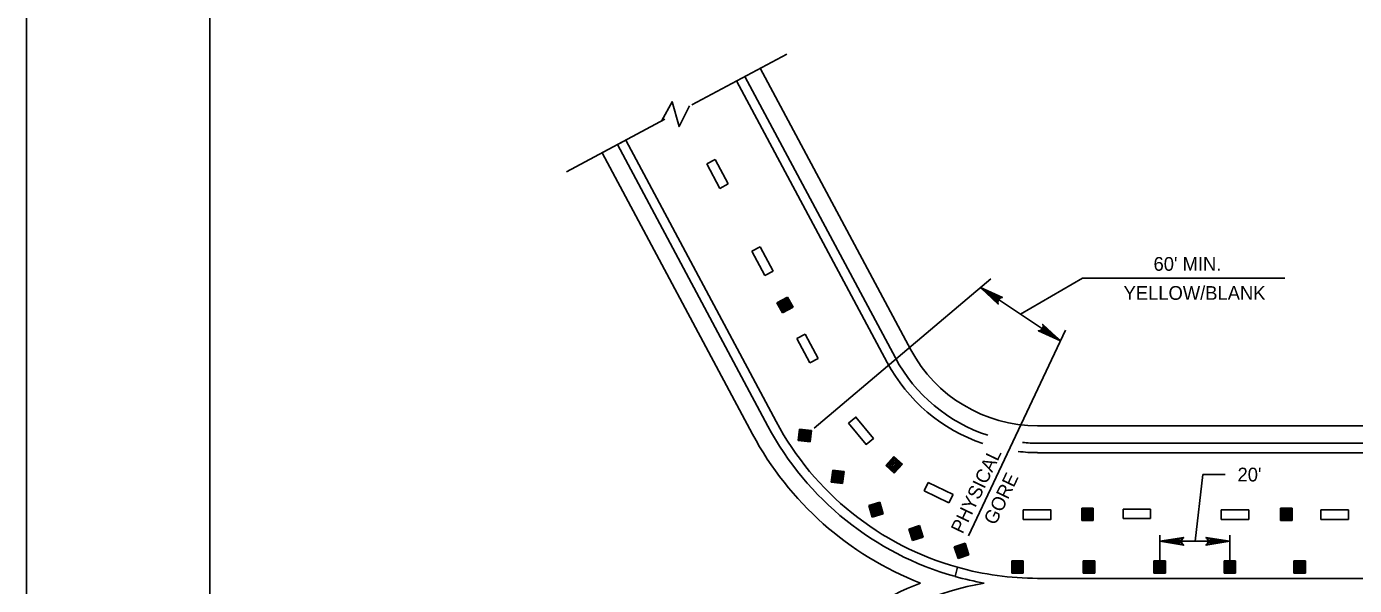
# Model space of a CAD drawing. Extents: x 639362 to 641108, y 298458 to 299646.
# Drawn here: x 639362.3 to 639652.3, y 299227.7 to 299349.9 of the extents above; entities that cross this region are included whole.
import ezdxf

# ---------------------------------------------------------------- set-up
doc = ezdxf.new("R2010")
doc.units = 0
for name, color, linetype in [('1', 7, 'Continuous'), ('2', 7, 'Continuous'), ('PLT-BNDY', 7, 'Continuous')]:
    doc.layers.add(name, color=color, linetype=linetype)

msp = doc.modelspace()

# ---------------------------------------------------------------- linework, layer by layer
at = {"layer": '1'}
msp.add_line((639402.31, 299630.63), (639402.31, 299066.63), dxfattribs=at)
at = {"layer": '2'}
for p, q in [((639507.56, 299332.75), (639528.33, 299343.84)), ((639555.38, 299279.23), (639522.52, 299340.74)), ((639550.22, 299276.47), (639517.36, 299337.98)), ((639552.04, 299277.45), (639519.18, 299338.95)), ((639480.23, 299318.14), (639501.69, 299329.61)), ((639493.13, 299325.03), (639491.31, 299324.06)), ((639491.31, 299324.06), (639524.18, 299262.56)), ((639526, 299263.53), (639493.13, 299325.03)), ((639520.84, 299260.77), (639487.97, 299322.28)), ((639510.86, 299319.82), (639512.69, 299320.78)), ((639513.67, 299314.5), (639510.86, 299319.82)), ((639512.69, 299320.78), (639515.49, 299315.46)), ((639515.49, 299315.46), (639513.67, 299314.5)), ((639520.7, 299300.75), (639522.53, 299301.71)), ((639523.5, 299295.43), (639520.7, 299300.75)), ((639522.53, 299301.71), (639525.33, 299296.39)), ((639525.33, 299296.39), (639523.5, 299295.43)), ((639534.31, 299262.09), (639572.85, 299294.76)), ((639579.34, 299287), (639592.87, 299294.89)), ((639592.87, 299294.89), (639637.03, 299294.89)), ((639526.16, 299289.48), (639528.5, 299290.73)), ((639526.36, 299289.38), (639528.47, 299290.51)), ((639528.47, 299290.51), (639529.48, 299288.63)), ((639528.5, 299290.73), (639529.68, 299288.53)), ((639570.58, 299292.84), (639588.1, 299281.16)), ((639527.34, 299287.28), (639526.16, 299289.48)), ((639527.37, 299287.5), (639526.36, 299289.38)), ((639526.6, 299289.3), (639528.4, 299290.27)), ((639527.44, 299287.74), (639526.6, 299289.3)), ((639526.84, 299289.23), (639528.33, 299290.03)), ((639527.51, 299287.98), (639526.84, 299289.23)), ((639527.08, 299289.16), (639528.25, 299289.79)), ((639527.58, 299288.22), (639527.08, 299289.16)), ((639527.32, 299289.09), (639528.18, 299289.55)), ((639527.66, 299288.46), (639527.32, 299289.09)), ((639529.68, 299288.53), (639527.34, 299287.28)), ((639529.48, 299288.63), (639527.37, 299287.5)), ((639529.24, 299288.7), (639527.44, 299287.74)), ((639529, 299288.78), (639527.51, 299287.98)), ((639527.56, 299289.01), (639528.11, 299289.31)), ((639527.73, 299288.7), (639527.56, 299289.01)), ((639528.76, 299288.85), (639527.58, 299288.22)), ((639528.52, 299288.92), (639527.66, 299288.46)), ((639528.28, 299288.99), (639527.73, 299288.7)), ((639528.04, 299289.07), (639527.8, 299288.94)), ((639528.11, 299289.31), (639528.28, 299288.99)), ((639528.18, 299289.55), (639528.52, 299288.92)), ((639528.25, 299289.79), (639528.76, 299288.85)), ((639528.33, 299290.03), (639529, 299288.78)), ((639528.4, 299290.27), (639529.24, 299288.7)), ((639530.53, 299281.68), (639532.36, 299282.65)), ((639532.36, 299282.65), (639535.16, 299277.33)), ((639568.01, 299238.58), (639589.2, 299283.5)), ((639533.34, 299276.36), (639530.53, 299281.68)), ((639535.16, 299277.33), (639533.34, 299276.36)), ((639530.8, 299259.39), (639531.06, 299261.87)), ((639530.95, 299259.56), (639531.17, 299261.68)), ((639531.06, 299261.87), (639533.7, 299261.59)), ((639531.14, 299259.72), (639531.33, 299261.48)), ((639531.17, 299261.68), (639533.55, 299261.43)), ((639531.33, 299261.48), (639533.36, 299261.27)), ((639533.7, 299261.59), (639533.44, 299259.11)), ((639583.1, 299262.59), (639789.68, 299262.59)), ((639533.44, 299259.11), (639530.8, 299259.39)), ((639533.33, 299259.31), (639530.95, 299259.56)), ((639533.17, 299259.51), (639531.14, 299259.72)), ((639531.34, 299259.88), (639531.49, 299261.29)), ((639533.02, 299259.7), (639531.34, 299259.88)), ((639531.49, 299261.29), (639533.17, 299261.11)), ((639531.53, 299260.03), (639531.65, 299261.09)), ((639532.86, 299259.89), (639531.53, 299260.03)), ((639531.65, 299261.09), (639532.97, 299260.95)), ((639531.73, 299260.19), (639531.8, 299260.9)), ((639532.7, 299260.09), (639531.73, 299260.19)), ((639531.8, 299260.9), (639532.78, 299260.8)), ((639531.93, 299260.35), (639531.96, 299260.7)), ((639532.54, 299260.29), (639531.93, 299260.35)), ((639531.96, 299260.7), (639532.58, 299260.64)), ((639532.12, 299260.51), (639532.38, 299260.48)), ((639532.58, 299260.64), (639532.54, 299260.29)), ((639532.78, 299260.8), (639532.7, 299260.09)), ((639532.97, 299260.95), (639532.86, 299259.89)), ((639533.17, 299261.11), (639533.02, 299259.7)), ((639533.36, 299261.27), (639533.17, 299259.51)), ((639533.55, 299261.43), (639533.33, 299259.31)), ((639583.09, 299258.81), (639789.68, 299258.81)), ((639549.93, 299253.95), (639551.72, 299255.91)), ((639550.15, 299253.92), (639551.77, 299255.69)), ((639551.72, 299255.91), (639553.56, 299254.22)), ((639551.77, 299255.69), (639553.34, 299254.25)), ((639583.09, 299256.74), (639789.68, 299256.74)), ((639538.03, 299250.32), (639538.4, 299252.95)), ((639538.23, 299250.43), (639538.57, 299252.8)), ((639538.4, 299252.95), (639540.87, 299252.6)), ((639538.57, 299252.8), (639540.67, 299252.5)), ((639551.77, 299252.27), (639549.93, 299253.95)), ((639551.72, 299252.48), (639550.15, 299253.92)), ((639550.41, 299253.93), (639551.78, 299255.44)), ((639551.71, 299252.74), (639550.41, 299253.93)), ((639550.65, 299253.94), (639551.79, 299255.19)), ((639551.7, 299252.99), (639550.65, 299253.94)), ((639550.9, 299253.96), (639551.8, 299254.94)), ((639551.69, 299253.24), (639550.9, 299253.96)), ((639551.15, 299253.97), (639551.81, 299254.69)), ((639551.68, 299253.49), (639551.15, 299253.97)), ((639551.41, 299253.98), (639551.83, 299254.43)), ((639551.67, 299253.74), (639551.41, 299253.98)), ((639551.84, 299254.19), (639551.66, 299253.99)), ((639552.09, 299254.19), (639551.67, 299253.74)), ((639552.34, 299254.21), (639551.68, 299253.49)), ((639552.59, 299254.22), (639551.69, 299253.24)), ((639552.84, 299254.23), (639551.7, 299252.99)), ((639553.09, 299254.24), (639551.71, 299252.74)), ((639553.34, 299254.25), (639551.72, 299252.48)), ((639553.56, 299254.22), (639551.77, 299252.27)), ((639551.78, 299255.44), (639553.09, 299254.24)), ((639551.79, 299255.19), (639552.84, 299254.23)), ((639551.8, 299254.94), (639552.59, 299254.22)), ((639551.81, 299254.69), (639552.34, 299254.21)), ((639551.83, 299254.43), (639552.09, 299254.19)), ((639540.5, 299249.98), (639538.03, 299250.32)), ((639540.34, 299250.13), (639538.23, 299250.43)), ((639538.43, 299250.58), (639538.71, 299252.6)), ((639540.19, 299250.33), (639538.43, 299250.58)), ((639538.63, 299250.73), (639538.87, 299252.4)), ((639540.04, 299250.53), (639538.63, 299250.73)), ((639538.71, 299252.6), (639540.47, 299252.35)), ((639538.83, 299250.88), (639539.02, 299252.2)), ((639539.89, 299250.73), (639538.83, 299250.88)), ((639538.87, 299252.4), (639540.27, 299252.2)), ((639539.02, 299252.2), (639540.07, 299252.05)), ((639539.03, 299251.03), (639539.17, 299252)), ((639539.74, 299250.94), (639539.03, 299251.03)), ((639539.17, 299252), (639539.87, 299251.9)), ((639539.23, 299251.18), (639539.32, 299251.8)), ((639539.58, 299251.14), (639539.23, 299251.18)), ((639539.32, 299251.8), (639539.67, 299251.75)), ((639539.43, 299251.34), (639539.47, 299251.6)), ((639539.67, 299251.75), (639539.58, 299251.14)), ((639539.87, 299251.9), (639539.74, 299250.94)), ((639540.07, 299252.05), (639539.89, 299250.73)), ((639540.27, 299252.2), (639540.04, 299250.53)), ((639540.47, 299252.35), (639540.19, 299250.33)), ((639540.67, 299252.5), (639540.34, 299250.13)), ((639540.87, 299252.6), (639540.5, 299249.98)), ((639558.31, 299248.37), (639559.21, 299250.23)), ((639559.21, 299250.23), (639564.62, 299247.61)), ((639619.18, 299251.99), (639617.48, 299237.38)), ((639619.18, 299251.99), (639624.04, 299251.99)), ((639563.72, 299245.75), (639558.31, 299248.37)), ((639564.62, 299247.61), (639563.72, 299245.75)), ((639546.25, 299245.23), (639548.65, 299245.91)), ((639546.97, 299242.68), (639546.25, 299245.23)), ((639546.46, 299245.16), (639548.51, 299245.74)), ((639547.11, 299242.85), (639546.46, 299245.16)), ((639546.68, 299245.03), (639548.39, 299245.51)), ((639547.23, 299243.07), (639546.68, 299245.03)), ((639546.9, 299244.91), (639548.26, 299245.3)), ((639547.36, 299243.29), (639546.9, 299244.91)), ((639547.12, 299244.79), (639548.14, 299245.08)), ((639547.48, 299243.51), (639547.12, 299244.79)), ((639547.34, 299244.67), (639548.02, 299244.86)), ((639547.6, 299243.73), (639547.34, 299244.67)), ((639547.55, 299244.54), (639547.9, 299244.64)), ((639547.72, 299243.95), (639547.55, 299244.54)), ((639547.85, 299244.17), (639547.78, 299244.42)), ((639547.9, 299244.64), (639548.06, 299244.04)), ((639548.02, 299244.86), (639548.29, 299243.92)), ((639548.14, 299245.08), (639548.5, 299243.8)), ((639548.26, 299245.3), (639548.72, 299243.68)), ((639548.39, 299245.51), (639548.94, 299243.55)), ((639548.51, 299245.74), (639549.16, 299243.43)), ((639548.65, 299245.91), (639549.37, 299243.35)), ((639592.74, 299244.59), (639595.23, 299244.59)), ((639592.74, 299241.93), (639592.74, 299244.59)), ((639592.92, 299244.45), (639595.05, 299244.45)), ((639592.92, 299242.06), (639592.92, 299244.45)), ((639593.1, 299244.28), (639594.87, 299244.28)), ((639593.1, 299242.24), (639593.1, 299244.28)), ((639593.28, 299244.1), (639594.7, 299244.1)), ((639593.28, 299242.41), (639593.28, 299244.1)), ((639594.7, 299244.1), (639594.7, 299242.41)), ((639594.87, 299244.28), (639594.87, 299242.24)), ((639595.05, 299244.45), (639595.05, 299242.06)), ((639595.23, 299244.59), (639595.23, 299241.93)), ((639601.74, 299242.34), (639601.74, 299244.4)), ((639601.74, 299244.4), (639607.75, 299244.4)), ((639607.75, 299244.4), (639607.75, 299242.34)), ((639623.19, 299242.15), (639623.19, 299244.22)), ((639623.19, 299244.22), (639629.21, 299244.22)), ((639629.21, 299244.22), (639629.21, 299242.15)), ((639638.65, 299244.59), (639636.15, 299244.59)), ((639636.15, 299244.59), (639636.15, 299241.93)), ((639638.46, 299244.45), (639636.33, 299244.45)), ((639636.33, 299244.45), (639636.33, 299242.06)), ((639638.28, 299244.28), (639636.51, 299244.28)), ((639636.51, 299244.28), (639636.51, 299242.24)), ((639638.1, 299244.1), (639636.69, 299244.1)), ((639636.69, 299244.1), (639636.69, 299242.41)), ((639638.1, 299242.41), (639638.1, 299244.1)), ((639638.28, 299242.24), (639638.28, 299244.28)), ((639638.46, 299242.06), (639638.46, 299244.45)), ((639638.65, 299241.93), (639638.65, 299244.59)), ((639644.92, 299242.15), (639644.92, 299244.22)), ((639644.92, 299244.22), (639650.93, 299244.22)), ((639650.93, 299244.22), (639650.93, 299242.15)), ((639549.37, 299243.35), (639546.97, 299242.68)), ((639549.16, 299243.43), (639547.11, 299242.85)), ((639548.94, 299243.55), (639547.23, 299243.07)), ((639548.72, 299243.68), (639547.36, 299243.29)), ((639548.5, 299243.8), (639547.48, 299243.51)), ((639548.29, 299243.92), (639547.6, 299243.73)), ((639548.06, 299244.04), (639547.72, 299243.95)), ((639595.23, 299241.93), (639592.74, 299241.93)), ((639595.05, 299242.06), (639592.92, 299242.06)), ((639594.87, 299242.24), (639593.1, 299242.24)), ((639594.7, 299242.41), (639593.28, 299242.41)), ((639593.45, 299243.92), (639594.52, 299243.92)), ((639593.45, 299242.59), (639593.45, 299243.92)), ((639594.52, 299242.59), (639593.45, 299242.59)), ((639593.63, 299242.77), (639593.63, 299243.74)), ((639593.63, 299243.74), (639594.34, 299243.74)), ((639594.34, 299242.77), (639593.63, 299242.77)), ((639593.81, 299243.57), (639594.17, 299243.57)), ((639593.81, 299242.95), (639593.81, 299243.57)), ((639594.17, 299242.95), (639593.81, 299242.95)), ((639593.99, 299243.39), (639593.99, 299243.12)), ((639594.17, 299243.57), (639594.17, 299242.95)), ((639594.34, 299243.74), (639594.34, 299242.77)), ((639594.52, 299243.92), (639594.52, 299242.59)), ((639607.75, 299242.34), (639601.74, 299242.34)), ((639629.21, 299242.15), (639623.19, 299242.15)), ((639636.15, 299241.93), (639638.65, 299241.93)), ((639636.33, 299242.06), (639638.46, 299242.06)), ((639636.51, 299242.24), (639638.28, 299242.24)), ((639636.69, 299242.41), (639638.1, 299242.41)), ((639637.93, 299243.92), (639636.86, 299243.92)), ((639636.86, 299243.92), (639636.86, 299242.59)), ((639636.86, 299242.59), (639637.93, 299242.59)), ((639637.04, 299243.74), (639637.04, 299242.77)), ((639637.75, 299243.74), (639637.04, 299243.74)), ((639637.04, 299242.77), (639637.75, 299242.77)), ((639637.57, 299243.57), (639637.22, 299243.57)), ((639637.22, 299243.57), (639637.22, 299242.95)), ((639637.22, 299242.95), (639637.57, 299242.95)), ((639637.4, 299243.39), (639637.4, 299243.12)), ((639637.57, 299242.95), (639637.57, 299243.57)), ((639637.75, 299242.77), (639637.75, 299243.74)), ((639637.93, 299242.59), (639637.93, 299243.92)), ((639650.93, 299242.15), (639644.92, 299242.15)), ((639554.93, 299240.05), (639557.31, 299240.82)), ((639555.75, 299237.52), (639554.93, 299240.05)), ((639555.14, 299239.98), (639557.17, 299240.64)), ((639555.88, 299237.71), (639555.14, 299239.98)), ((639555.37, 299239.87), (639557.05, 299240.41)), ((639555.99, 299237.93), (639555.37, 299239.87)), ((639555.59, 299239.76), (639556.94, 299240.19)), ((639556.11, 299238.15), (639555.59, 299239.76)), ((639558.12, 299238.29), (639555.75, 299237.52)), ((639555.81, 299239.64), (639556.83, 299239.97)), ((639556.22, 299238.37), (639555.81, 299239.64)), ((639557.9, 299238.36), (639555.88, 299237.71)), ((639557.68, 299238.47), (639555.99, 299237.93)), ((639556.03, 299239.53), (639556.71, 299239.75)), ((639556.33, 299238.6), (639556.03, 299239.53)), ((639557.46, 299238.59), (639556.11, 299238.15)), ((639557.24, 299238.7), (639556.22, 299238.37)), ((639556.26, 299239.41), (639556.6, 299239.52)), ((639556.45, 299238.82), (639556.26, 299239.41)), ((639557.01, 299238.82), (639556.33, 299238.6)), ((639556.79, 299238.93), (639556.45, 299238.82)), ((639556.57, 299239.04), (639556.48, 299239.3)), ((639556.6, 299239.52), (639556.79, 299238.93)), ((639556.71, 299239.75), (639557.01, 299238.82)), ((639556.83, 299239.97), (639557.24, 299238.7)), ((639556.94, 299240.19), (639557.46, 299238.59)), ((639557.05, 299240.41), (639557.68, 299238.47)), ((639557.17, 299240.64), (639557.9, 299238.36)), ((639557.31, 299240.82), (639558.12, 299238.29)), ((639609.74, 299238.7), (639609.74, 299232.09)), ((639625.08, 299238.7), (639625.08, 299232.09)), ((639564.89, 299236.17), (639567.26, 299236.94)), ((639565.7, 299233.64), (639564.89, 299236.17)), ((639565.1, 299236.1), (639567.13, 299236.76)), ((639565.84, 299233.83), (639565.1, 299236.1)), ((639565.32, 299235.99), (639567.01, 299236.53)), ((639565.95, 299234.05), (639565.32, 299235.99)), ((639565.55, 299235.88), (639566.9, 299236.31)), ((639566.07, 299234.27), (639565.55, 299235.88)), ((639565.77, 299235.76), (639566.78, 299236.09)), ((639566.18, 299234.49), (639565.77, 299235.76)), ((639565.99, 299235.65), (639566.67, 299235.87)), ((639566.29, 299234.72), (639565.99, 299235.65)), ((639566.22, 299235.53), (639566.55, 299235.64)), ((639566.41, 299234.94), (639566.22, 299235.53)), ((639566.52, 299235.16), (639566.44, 299235.42)), ((639566.55, 299235.64), (639566.74, 299235.05)), ((639566.67, 299235.87), (639566.97, 299234.94)), ((639566.78, 299236.09), (639567.19, 299234.82)), ((639566.9, 299236.31), (639567.41, 299234.71)), ((639567.01, 299236.53), (639567.64, 299234.59)), ((639567.13, 299236.76), (639567.86, 299234.48)), ((639567.26, 299236.94), (639568.08, 299234.41)), ((639609.74, 299237.38), (639625.08, 299237.38)), ((639568.08, 299234.41), (639565.7, 299233.64)), ((639567.86, 299234.48), (639565.84, 299233.83)), ((639567.64, 299234.59), (639565.95, 299234.05)), ((639567.41, 299234.71), (639566.07, 299234.27)), ((639567.19, 299234.82), (639566.18, 299234.49)), ((639566.97, 299234.94), (639566.29, 299234.72)), ((639566.74, 299235.05), (639566.41, 299234.94)), ((639577.44, 299230.43), (639577.44, 299233.09)), ((639577.44, 299233.09), (639579.94, 299233.09)), ((639577.62, 299230.57), (639577.62, 299232.96)), ((639577.62, 299232.96), (639579.75, 299232.96)), ((639577.8, 299230.74), (639577.8, 299232.78)), ((639577.8, 299232.78), (639579.57, 299232.78)), ((639577.98, 299230.92), (639577.98, 299232.61)), ((639577.98, 299232.61), (639579.4, 299232.61)), ((639579.4, 299232.61), (639579.4, 299230.92)), ((639579.57, 299232.78), (639579.57, 299230.74)), ((639579.75, 299232.96), (639579.75, 299230.57)), ((639579.94, 299233.09), (639579.94, 299230.43)), ((639593.04, 299230.43), (639593.04, 299233.09)), ((639593.04, 299233.09), (639595.54, 299233.09)), ((639593.23, 299230.57), (639593.23, 299232.96)), ((639593.23, 299232.96), (639595.35, 299232.96)), ((639593.4, 299230.74), (639593.4, 299232.78)), ((639593.4, 299232.78), (639595.18, 299232.78)), ((639593.58, 299230.92), (639593.58, 299232.61)), ((639593.58, 299232.61), (639595, 299232.61)), ((639595, 299232.61), (639595, 299230.92)), ((639595.18, 299232.78), (639595.18, 299230.74)), ((639595.35, 299232.96), (639595.35, 299230.57)), ((639595.54, 299233.09), (639595.54, 299230.43)), ((639610.97, 299233.09), (639608.47, 299233.09)), ((639608.47, 299233.09), (639608.47, 299230.43)), ((639610.79, 299232.96), (639608.66, 299232.96)), ((639608.66, 299232.96), (639608.66, 299230.57)), ((639610.61, 299232.78), (639608.84, 299232.78)), ((639608.84, 299232.78), (639608.84, 299230.74)), ((639610.43, 299232.61), (639609.01, 299232.61)), ((639609.01, 299232.61), (639609.01, 299230.92)), ((639610.43, 299230.92), (639610.43, 299232.61)), ((639610.61, 299230.74), (639610.61, 299232.78)), ((639610.79, 299230.57), (639610.79, 299232.96)), ((639610.97, 299230.43), (639610.97, 299233.09)), ((639626.31, 299233.09), (639623.81, 299233.09)), ((639623.81, 299233.09), (639623.81, 299230.43)), ((639626.12, 299232.96), (639623.99, 299232.96)), ((639623.99, 299232.96), (639623.99, 299230.57)), ((639625.95, 299232.78), (639624.17, 299232.78)), ((639624.17, 299232.78), (639624.17, 299230.74)), ((639625.77, 299232.61), (639624.35, 299232.61)), ((639624.35, 299232.61), (639624.35, 299230.92)), ((639625.77, 299230.92), (639625.77, 299232.61)), ((639625.95, 299230.74), (639625.95, 299232.78)), ((639626.12, 299230.57), (639626.12, 299232.96)), ((639626.31, 299230.43), (639626.31, 299233.09)), ((639639.06, 299230.43), (639639.06, 299233.09)), ((639639.06, 299233.09), (639641.55, 299233.09)), ((639639.24, 299230.57), (639639.24, 299232.96)), ((639639.24, 299232.96), (639641.37, 299232.96)), ((639639.42, 299230.74), (639639.42, 299232.78)), ((639639.42, 299232.78), (639641.19, 299232.78)), ((639639.6, 299230.92), (639639.6, 299232.61)), ((639639.6, 299232.61), (639641.01, 299232.61)), ((639641.01, 299232.61), (639641.01, 299230.92)), ((639641.19, 299232.78), (639641.19, 299230.74)), ((639641.37, 299232.96), (639641.37, 299230.57)), ((639641.55, 299233.09), (639641.55, 299230.43)), ((639565.05, 299229.71), (639565.61, 299231.69)), ((639579.94, 299230.43), (639577.44, 299230.43)), ((639579.75, 299230.57), (639577.62, 299230.57)), ((639579.57, 299230.74), (639577.8, 299230.74)), ((639579.4, 299230.92), (639577.98, 299230.92)), ((639578.16, 299231.1), (639578.16, 299232.43)), ((639578.16, 299232.43), (639579.22, 299232.43)), ((639579.22, 299231.1), (639578.16, 299231.1)), ((639578.33, 299231.28), (639578.33, 299232.25)), ((639578.33, 299232.25), (639579.04, 299232.25)), ((639579.04, 299231.28), (639578.33, 299231.28)), ((639578.51, 299231.45), (639578.51, 299232.07)), ((639578.51, 299232.07), (639578.86, 299232.07)), ((639578.86, 299231.45), (639578.51, 299231.45)), ((639578.69, 299231.63), (639578.69, 299231.9)), ((639578.86, 299232.07), (639578.86, 299231.45)), ((639579.04, 299232.25), (639579.04, 299231.28)), ((639579.22, 299232.43), (639579.22, 299231.1)), ((639595.54, 299230.43), (639593.04, 299230.43)), ((639595.35, 299230.57), (639593.23, 299230.57)), ((639595.18, 299230.74), (639593.4, 299230.74)), ((639595, 299230.92), (639593.58, 299230.92)), ((639593.76, 299231.1), (639593.76, 299232.43)), ((639593.76, 299232.43), (639594.82, 299232.43)), ((639594.82, 299231.1), (639593.76, 299231.1)), ((639593.93, 299231.28), (639593.93, 299232.25)), ((639593.93, 299232.25), (639594.65, 299232.25)), ((639594.65, 299231.28), (639593.93, 299231.28)), ((639594.11, 299231.45), (639594.11, 299232.07)), ((639594.11, 299232.07), (639594.47, 299232.07)), ((639594.47, 299231.45), (639594.11, 299231.45)), ((639594.29, 299231.63), (639594.29, 299231.9)), ((639594.47, 299232.07), (639594.47, 299231.45)), ((639594.65, 299232.25), (639594.65, 299231.28)), ((639594.82, 299232.43), (639594.82, 299231.1)), ((639608.47, 299230.43), (639610.97, 299230.43)), ((639608.66, 299230.57), (639610.79, 299230.57)), ((639608.84, 299230.74), (639610.61, 299230.74)), ((639609.01, 299230.92), (639610.43, 299230.92)), ((639610.25, 299232.43), (639609.19, 299232.43)), ((639609.19, 299232.43), (639609.19, 299231.1)), ((639609.19, 299231.1), (639610.25, 299231.1)), ((639610.08, 299232.25), (639609.37, 299232.25)), ((639609.37, 299232.25), (639609.37, 299231.28)), ((639609.37, 299231.28), (639610.08, 299231.28)), ((639609.9, 299232.07), (639609.55, 299232.07)), ((639609.55, 299232.07), (639609.55, 299231.45)), ((639609.55, 299231.45), (639609.9, 299231.45)), ((639609.72, 299231.63), (639609.72, 299231.9)), ((639609.9, 299231.45), (639609.9, 299232.07)), ((639610.08, 299231.28), (639610.08, 299232.25)), ((639610.25, 299231.1), (639610.25, 299232.43)), ((639623.81, 299230.43), (639626.31, 299230.43)), ((639623.99, 299230.57), (639626.12, 299230.57)), ((639624.17, 299230.74), (639625.95, 299230.74)), ((639624.35, 299230.92), (639625.77, 299230.92)), ((639625.59, 299232.43), (639624.53, 299232.43)), ((639624.53, 299232.43), (639624.53, 299231.1)), ((639624.53, 299231.1), (639625.59, 299231.1)), ((639625.42, 299232.25), (639624.7, 299232.25)), ((639624.7, 299232.25), (639624.7, 299231.28)), ((639624.7, 299231.28), (639625.42, 299231.28)), ((639625.24, 299232.07), (639624.88, 299232.07)), ((639624.88, 299232.07), (639624.88, 299231.45)), ((639624.88, 299231.45), (639625.24, 299231.45)), ((639625.06, 299231.63), (639625.06, 299231.9)), ((639625.24, 299231.45), (639625.24, 299232.07)), ((639625.42, 299231.28), (639625.42, 299232.25)), ((639625.59, 299231.1), (639625.59, 299232.43)), ((639641.55, 299230.43), (639639.06, 299230.43)), ((639641.37, 299230.57), (639639.24, 299230.57)), ((639641.19, 299230.74), (639639.42, 299230.74)), ((639641.01, 299230.92), (639639.6, 299230.92)), ((639639.77, 299231.1), (639639.77, 299232.43)), ((639639.77, 299232.43), (639640.84, 299232.43)), ((639640.84, 299231.1), (639639.77, 299231.1)), ((639639.95, 299231.28), (639639.95, 299232.25)), ((639639.95, 299232.25), (639640.66, 299232.25)), ((639640.66, 299231.28), (639639.95, 299231.28)), ((639640.13, 299231.45), (639640.13, 299232.07)), ((639640.13, 299232.07), (639640.48, 299232.07)), ((639640.48, 299231.45), (639640.13, 299231.45)), ((639640.3, 299231.63), (639640.3, 299231.9)), ((639640.48, 299232.07), (639640.48, 299231.45)), ((639640.66, 299232.25), (639640.66, 299231.28)), ((639640.84, 299232.43), (639640.84, 299231.1)), ((639583.05, 299229.28), (639672.74, 299229.28))]:
    msp.add_line(p, q, dxfattribs=at)
for points in [[(639501.02, 299329.35), (639503.25, 299333.42), (639504.81, 299328), (639507.1, 299332.53)], [(639574.39, 299289.55), (639574.43, 299289.95), (639570.58, 299292.84), (639574.39, 299289.55), (639574.48, 299289.22), (639570.58, 299292.84), (639574.71, 299290.37), (639575.05, 299290.57), (639570.58, 299292.84), (639575.41, 299290.62), (639575.05, 299290.57)], [(639584.29, 299284.45), (639584.24, 299284.05), (639588.1, 299281.16), (639584.29, 299284.45), (639584.2, 299284.78), (639588.1, 299281.16), (639583.97, 299283.63), (639583.62, 299283.43), (639588.1, 299281.16), (639583.27, 299283.38), (639583.62, 299283.43)], [(639614.74, 299236.75), (639614.55, 299237.11), (639609.74, 299237.38), (639614.74, 299236.75), (639614.99, 299236.53), (639609.74, 299237.38), (639614.55, 299237.62), (639614.72, 299237.97), (639609.74, 299237.38), (639614.99, 299238.21), (639614.72, 299237.97)], [(639620.08, 299238), (639620.27, 299237.64), (639625.08, 299237.38), (639620.08, 299238), (639619.83, 299238.22), (639625.08, 299237.38), (639620.27, 299237.14), (639620.1, 299236.78), (639625.08, 299237.38), (639619.83, 299236.54), (639620.1, 299236.78)]]:
    msp.add_lwpolyline(points, dxfattribs=at)
for points in [[(639541.8, 299263.21), (639543.4, 299264.52), (639547.21, 299259.86), (639545.61, 299258.56)], [(639579.96, 299244.22), (639585.97, 299244.22), (639585.97, 299242.15), (639579.96, 299242.15)]]:
    msp.add_lwpolyline(points, close=True, dxfattribs=at)
for centre, radius, start, end in [((639583.13, 299294.06), 31.46, 208.1179, 269.9284), ((639583.13, 299294.06), 37.31, 208.1179, 251.2489), ((639583.13, 299294.06), 35.25, 208.1179, 251.9444), ((639583.13, 299294.06), 66.85, 208.1179, 254.2131), ((639583.13, 299294.06), 64.78, 208.1179, 254.3067), ((639583.13, 299294.06), 70.63, 208.1179, 248.7197), ((639583.13, 299294.06), 35.25, 264.5437, 269.9284), ((639583.13, 299294.06), 37.31, 263.3923, 269.9284), ((639583.13, 299294.06), 66.85, 254.3067, 259.9292), ((639583.13, 299294.06), 64.78, 254.3067, 269.9284), ((639583.13, 299162.43), 70.63, 111.2803, 151.8821), ((639583.13, 299162.43), 66.85, 100.0708, 151.8821)]:
    msp.add_arc(centre, radius, start, end, dxfattribs=at)
at = {"layer": 'PLT-BNDY'}
msp.add_lwpolyline([(639362.31, 299645.63), (640203.31, 299645.63), (640203.31, 299051.63), (639362.31, 299051.63)], close=True, dxfattribs=at)

# ---------------------------------------------------------------- texts
at = {"layer": '2'}
for s, p in [("60' MIN.", (639608.39, 299296.49)), ('YELLOW/BLANK', (639601.85, 299290.14)), ("20'", (639626.73, 299250.46))]:
    msp.add_text(s, height=3, dxfattribs=at).set_placement(p)
for s, p in [('PHYSICAL', (639566.7, 299238.83)), ('GORE', (639573.89, 299240.74))]:
    msp.add_text(s, height=3, rotation=64.3716, dxfattribs=at).set_placement(p)

doc.saveas('drawing.dxf')
